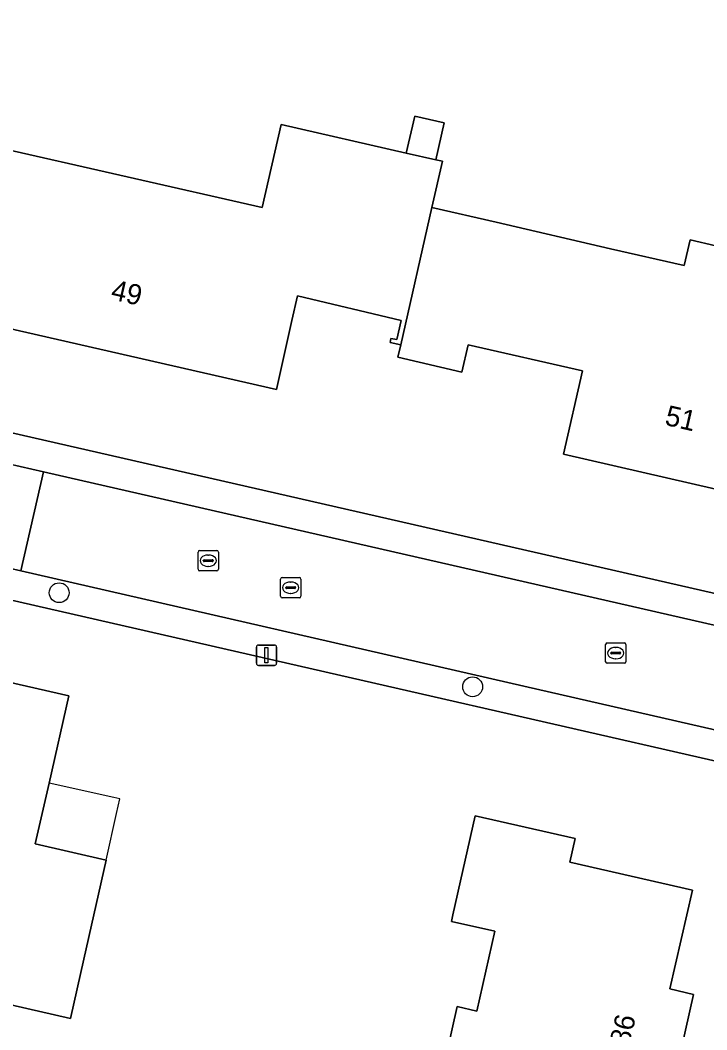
# Model space of a CAD drawing. Extents: x 159626 to 160723, y 388173 to 389416.
# Drawn here: x 160396 to 160429.82, y 388733.05 to 388782.82 of the extents above; entities that cross this region are included whole.
import ezdxf

# ---------------------------------------------------------------- set-up
doc = ezdxf.new("R2010")
doc.units = 0
for name, color, linetype in [('IMGEO_Boom', 7, 'Continuous'), ('IMGEO_Erf', 7, 'Continuous'), ('IMGEO_Kolk', 7, 'Continuous'), ('IMGEO_Lichtmast', 7, 'Continuous'), ('IMGEO_Pand', 7, 'Continuous'), ('IMGEO_Pand_nummerreeks', 7, 'Continuous'), ('IMGEO_Pand_overbouw', 7, 'Continuous'), ('IMGEO_Rijbaan_lokaal_open', 7, 'Continuous'), ('IMGEO_Rioolput', 7, 'Continuous'), ('IMGEO_Voetpad_open', 7, 'Continuous')]:
    doc.layers.add(name, color=color, linetype=linetype)

msp = doc.modelspace()

# ---------------------------------------------------------------- linework, layer by layer
at = {"layer": 'IMGEO_Boom'}
for centre in [(160397.915, 388754.598), (160418.282, 388749.962)]:
    msp.add_circle(centre, 0.489, dxfattribs=at)
at = {"layer": 'IMGEO_Erf'}
for points in [[(160449.167, 388778.98), (160349.516, 388801.899), (160343.31, 388774.43), (160440.005, 388752.323)], [(160392.575, 388734.957), (160393.424, 388738.673), (160388.01, 388739.91), (160389.499, 388746.422), (160390.318, 388750), (160390.614, 388751.296), (160396.298, 388750), (160398.39, 388749.523), (160397.417, 388745.217), (160396.738, 388742.213), (160400.222, 388741.414), (160399.131, 388736.535), (160398.476, 388733.609)], [(160417.518, 388734.199), (160418.495, 388733.98), (160419.375, 388737.916), (160417.236, 388738.394), (160417.309, 388738.721), (160418.4, 388743.6), (160423.34, 388742.48), (160423.074, 388741.321), (160429.107, 388739.939), (160428.004, 388735.068), (160429.16, 388734.792), (160428.124, 388730.172), (160426.983, 388730.428), (160425.237, 388722.669), (160426.398, 388722.448), (160426.317, 388722.151), (160421.438, 388723.242), (160415.372, 388724.598)]]:
    msp.add_lwpolyline(points, close=True, dxfattribs=at)
for points in [[(160394.605, 388776.617), (160407.92, 388773.589), (160408.85, 388777.68), (160415.016, 388776.274), (160415.43, 388778.089), (160416.882, 388777.758), (160416.468, 388775.943), (160416.79, 388775.87), (160416.269, 388773.595), (160419.442, 388772.868), (160425.077, 388771.558), (160428.709, 388770.727), (160428.999, 388771.993), (160430.265, 388771.704)], [(160432.905, 388759.098), (160422.761, 388761.434), (160423.698, 388765.529), (160418.056, 388766.817), (160417.748, 388765.471), (160414.604, 388766.208), (160414.748, 388766.816), (160414.219, 388766.928), (160414.258, 388767.127), (160414.546, 388767.076), (160414.763, 388768.023), (160409.649, 388769.24), (160409.376, 388768.015), (160408.618, 388764.617), (160392.702, 388768.247)], [(160434.137, 388717.28), (160434.072, 388718.873), (160433.987, 388720.982), (160434.735, 388725.886), (160435.774, 388729.256), (160435.848, 388729.496), (160438.137, 388741.543), (160438.297, 388742.385), (160438.675, 388744.375), (160414.083, 388750), (160341.5, 388766.603), (160337.712, 388750), (160328.964, 388711.66), (160336.388, 388709.95), (160341.104, 388708.866), (160384.636, 388698.856)]]:
    msp.add_lwpolyline(points, dxfattribs=at)
at = {"layer": 'IMGEO_Kolk'}
for p, q in [((160404.757, 388755.752), (160404.757, 388756.604)), ((160404.832, 388756.678), (160405.684, 388756.678)), ((160405.758, 388756.604), (160405.758, 388755.752)), ((160405.016, 388756.172), (160405.016, 388756.184)), ((160405.454, 388756.135), (160405.056, 388756.135)), ((160405.059, 388756.221), (160405.457, 388756.221)), ((160405.245, 388756.458), (160405.27, 388756.458)), ((160405.5, 388756.184), (160405.5, 388756.172)), ((160405.684, 388755.678), (160404.832, 388755.678)), ((160405.268, 388755.898), (160405.243, 388755.898)), ((160424.831, 388751.198), (160424.831, 388752.05)), ((160424.906, 388752.124), (160425.758, 388752.124)), ((160425.832, 388752.05), (160425.832, 388751.198)), ((160425.09, 388751.618), (160425.09, 388751.63)), ((160425.528, 388751.581), (160425.13, 388751.581)), ((160425.133, 388751.667), (160425.531, 388751.667)), ((160425.319, 388751.904), (160425.344, 388751.904)), ((160425.574, 388751.63), (160425.574, 388751.618)), ((160425.758, 388751.124), (160424.906, 388751.124)), ((160425.342, 388751.344), (160425.317, 388751.344))]:
    msp.add_line(p, q, dxfattribs=at)
for points in [[(160404.757, 388755.752), (160404.757, 388756.604)], [(160404.832, 388756.678), (160405.684, 388756.678)], [(160405.758, 388756.604), (160405.758, 388755.752)], [(160405.684, 388755.678), (160404.832, 388755.678)], [(160424.831, 388751.198), (160424.831, 388752.05)], [(160424.906, 388752.124), (160425.758, 388752.124)], [(160425.832, 388752.05), (160425.832, 388751.198)], [(160425.758, 388751.124), (160424.906, 388751.124)]]:
    msp.add_lwpolyline(points, dxfattribs=at)
for centre, radius, start, end in [((160404.834, 388756.602), 0.0765, 91.552, 178.448), ((160404.834, 388756.602), 0.0765, 91.552, 178.448), ((160405.682, 388756.602), 0.0765, 1.552, 88.448), ((160405.682, 388756.602), 0.0765, 1.552, 88.448), ((160405.056, 388756.181), 0.0403, 85.8775, 175.7526), ((160405.053, 388756.171), 0.0366, 178.938, 274.7102), ((160405.457, 388756.178), 0.043, 264.8664, 352.4533), ((160405.461, 388756.183), 0.0386, 1.7309, 96.639), ((160404.834, 388755.754), 0.0765, 181.552, 268.448), ((160404.834, 388755.754), 0.0765, 181.552, 268.448), ((160405.682, 388755.754), 0.0765, 271.552, 358.448), ((160405.682, 388755.754), 0.0765, 271.552, 358.448), ((160424.908, 388752.048), 0.0765, 91.552, 178.448), ((160424.908, 388752.048), 0.0765, 91.552, 178.448), ((160425.756, 388752.048), 0.0765, 1.552, 88.448), ((160425.756, 388752.048), 0.0765, 1.552, 88.448), ((160425.13, 388751.627), 0.0403, 85.8775, 175.7526), ((160425.127, 388751.617), 0.0366, 178.938, 274.7102), ((160425.531, 388751.624), 0.043, 264.8664, 352.4533), ((160425.535, 388751.629), 0.0386, 1.7309, 96.639), ((160424.908, 388751.2), 0.0765, 181.552, 268.448), ((160424.908, 388751.2), 0.0765, 181.552, 268.448), ((160425.756, 388751.2), 0.0765, 271.552, 358.448), ((160425.756, 388751.2), 0.0765, 271.552, 358.448)]:
    msp.add_arc(centre, radius, start, end, dxfattribs=at)
for centre, major_axis, ratio, start_param, end_param in [((160405.244, 388756.178), (-0.387, 0.002), 0.722429, 4.712389, 7.853982), ((160405.269, 388756.178), (-0.39, 0.002), 0.717154, 1.570796, 4.712389), ((160425.318, 388751.624), (-0.387, 0.002), 0.722429, 4.712389, 7.853982), ((160425.343, 388751.624), (-0.39, 0.002), 0.717154, 1.570796, 4.712389)]:
    msp.add_ellipse(centre, major_axis=major_axis, ratio=ratio, start_param=start_param, end_param=end_param, dxfattribs=at)
at = {"layer": 'IMGEO_Lichtmast'}
for p, q in [((160407.631, 388751.119), (160407.631, 388751.919)), ((160407.631, 388751.919), (160407.631, 388751.119)), ((160407.731, 388752.019), (160408.521, 388752.019)), ((160408.521, 388752.019), (160407.731, 388752.019)), ((160408.621, 388751.919), (160408.621, 388751.119)), ((160408.621, 388751.119), (160408.621, 388751.919)), ((160408.521, 388751.019), (160407.731, 388751.019)), ((160407.731, 388751.019), (160408.521, 388751.019))]:
    msp.add_line(p, q, dxfattribs=at)
msp.add_lwpolyline([(160408.051, 388751.894), (160408.201, 388751.894), (160408.201, 388751.144), (160408.051, 388751.144), (160408.051, 388751.894)], dxfattribs=at)
for centre, start, end in [((160407.731, 388751.919), 90, 180), ((160407.731, 388751.919), 90, 180), ((160408.521, 388751.919), 0, 90), ((160408.521, 388751.919), 360, 90), ((160407.731, 388751.119), 180, 270), ((160407.731, 388751.119), 180, 270), ((160408.521, 388751.119), 270, 0), ((160408.521, 388751.119), 270, 0)]:
    msp.add_arc(centre, 0.1, start, end, dxfattribs=at)
at = {"layer": 'IMGEO_Pand'}
for points in [[(160415.016, 388776.274), (160416.468, 388775.943), (160416.882, 388777.758), (160415.43, 388778.089)], [(160416.269, 388773.595), (160416.79, 388775.87), (160416.468, 388775.943), (160415.016, 388776.274), (160408.85, 388777.68), (160407.92, 388773.589), (160394.605, 388776.617), (160392.702, 388768.247), (160408.618, 388764.617), (160409.376, 388768.015), (160409.649, 388769.24), (160414.763, 388768.023), (160414.546, 388767.076), (160414.258, 388767.127), (160414.219, 388766.928), (160414.748, 388766.816)], [(160414.748, 388766.816), (160414.604, 388766.208), (160417.748, 388765.471), (160418.056, 388766.817), (160423.698, 388765.529), (160422.761, 388761.434), (160432.905, 388759.098), (160433.672, 388762.407), (160435.252, 388762.058), (160435.585, 388763.631), (160438.918, 388762.865), (160441.225, 388772.999), (160431.092, 388775.317), (160430.265, 388771.704), (160428.999, 388771.993), (160428.709, 388770.727), (160425.077, 388771.558), (160419.442, 388772.868), (160416.269, 388773.595)], [(160400.222, 388741.414), (160396.738, 388742.213), (160397.417, 388745.217), (160398.39, 388749.523), (160396.298, 388750), (160390.614, 388751.296), (160390.318, 388750), (160389.499, 388746.422), (160388.01, 388739.91), (160393.424, 388738.673), (160392.575, 388734.957), (160398.476, 388733.609), (160399.131, 388736.535)], [(160428.124, 388730.172), (160429.16, 388734.792), (160428.004, 388735.068), (160429.107, 388739.939), (160423.074, 388741.321), (160423.34, 388742.48), (160418.4, 388743.6), (160417.309, 388738.721), (160417.236, 388738.394), (160419.375, 388737.916), (160418.495, 388733.98), (160417.518, 388734.199), (160415.372, 388724.598), (160421.438, 388723.242), (160426.317, 388722.151), (160426.398, 388722.448), (160425.237, 388722.669), (160426.983, 388730.428)]]:
    msp.add_lwpolyline(points, close=True, dxfattribs=at)
at = {"layer": 'IMGEO_Pand_overbouw'}
msp.add_lwpolyline([(160397.417, 388745.217), (160396.738, 388742.213), (160400.222, 388741.414), (160400.747, 388743.715), (160400.91, 388744.433), (160400.613, 388744.503)], close=True, dxfattribs=at)
at = {"layer": 'IMGEO_Rijbaan_lokaal_open'}
for points in [[(160396.029, 388755.673), (160397.147, 388760.561), (160394.255, 388761.223), (160393.137, 388756.335)], [(160397.147, 388760.561), (160396.029, 388755.673), (160420.804, 388750), (160440.901, 388745.398), (160441.513, 388747.903), (160442.094, 388750.278)]]:
    msp.add_lwpolyline(points, close=True, dxfattribs=at)
at = {"layer": 'IMGEO_Rioolput'}
for p, q in [((160408.821, 388754.421), (160408.821, 388755.273)), ((160408.896, 388755.347), (160409.748, 388755.347)), ((160409.309, 388755.127), (160409.334, 388755.127)), ((160409.822, 388755.273), (160409.822, 388754.421)), ((160409.08, 388754.841), (160409.08, 388754.853)), ((160409.518, 388754.804), (160409.12, 388754.804)), ((160409.123, 388754.89), (160409.521, 388754.89)), ((160409.332, 388754.567), (160409.307, 388754.567)), ((160409.564, 388754.853), (160409.564, 388754.841)), ((160409.748, 388754.347), (160408.896, 388754.347))]:
    msp.add_line(p, q, dxfattribs=at)
for points in [[(160408.821, 388754.421), (160408.821, 388755.273)], [(160408.896, 388755.347), (160409.748, 388755.347)], [(160409.822, 388755.273), (160409.822, 388754.421)], [(160409.748, 388754.347), (160408.896, 388754.347)]]:
    msp.add_lwpolyline(points, dxfattribs=at)
for centre, radius, start, end in [((160408.898, 388755.271), 0.0765, 91.552, 178.448), ((160408.898, 388755.271), 0.0765, 91.552, 178.448), ((160409.746, 388755.271), 0.0765, 1.552, 88.448), ((160409.746, 388755.271), 0.0765, 1.552, 88.448), ((160409.12, 388754.85), 0.0403, 85.8775, 175.7526), ((160409.117, 388754.84), 0.0366, 178.938, 274.7102), ((160409.521, 388754.847), 0.043, 264.8664, 352.4533), ((160409.525, 388754.852), 0.0386, 1.7309, 96.639), ((160408.898, 388754.423), 0.0765, 181.552, 268.448), ((160408.898, 388754.423), 0.0765, 181.552, 268.448), ((160409.746, 388754.423), 0.0765, 271.552, 358.448), ((160409.746, 388754.423), 0.0765, 271.552, 358.448)]:
    msp.add_arc(centre, radius, start, end, dxfattribs=at)
for centre, major_axis, ratio, start_param, end_param in [((160409.308, 388754.847), (-0.387, 0.002), 0.722429, 4.712389, 7.853982), ((160409.333, 388754.847), (-0.39, 0.002), 0.717154, 1.570796, 4.712389)]:
    msp.add_ellipse(centre, major_axis=major_axis, ratio=ratio, start_param=start_param, end_param=end_param, dxfattribs=at)
at = {"layer": 'IMGEO_Voetpad_open'}
msp.add_lwpolyline([(160343.31, 388774.43), (160340.358, 388775.105), (160271.421, 388790.878), (160271.082, 388789.403), (160273.762, 388788.79), (160333.234, 388775.183), (160335.964, 388774.559), (160394.255, 388761.223), (160397.147, 388760.561), (160442.094, 388750.278), (160441.513, 388747.903), (160443.576, 388747.408), (160444.155, 388749.806), (160444.202, 388750), (160444.514, 388751.292), (160440.526, 388752.204), (160440.005, 388752.323)], close=True, dxfattribs=at)
msp.add_lwpolyline([(160255.721, 388786.324), (160259.096, 388785.469), (160338.544, 388767.28), (160341.5, 388766.603), (160414.083, 388750), (160438.675, 388744.375), (160442.626, 388743.471), (160442.976, 388744.923), (160443.576, 388747.408), (160441.513, 388747.903), (160440.901, 388745.398), (160420.804, 388750), (160396.029, 388755.673), (160393.137, 388756.335), (160334.849, 388769.683), (160332.119, 388770.308), (160272.649, 388783.925)], dxfattribs=at)

# ---------------------------------------------------------------- texts
at = {"layer": 'IMGEO_Pand_nummerreeks'}
for s, rotation, p in [('49', 347.1543, (160400.415, 388769.072)), ('51', 347.0318, (160427.703, 388762.882)), ('86', 77.3609, (160426.002, 388732.228))]:
    msp.add_text(s, height=1, rotation=rotation, dxfattribs=at).set_placement(p)

doc.saveas('drawing.dxf')
